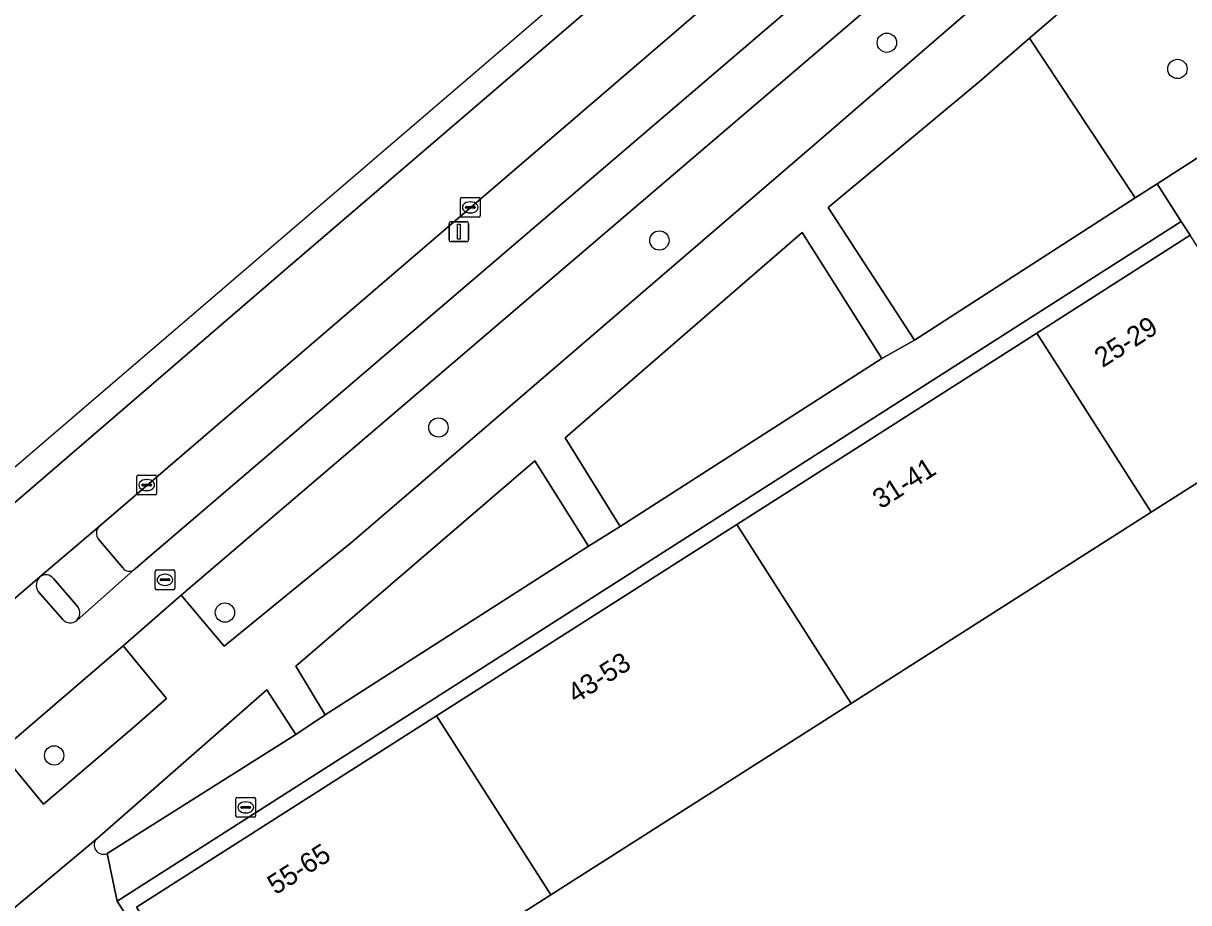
# Model space of a CAD drawing. Extents: x 159217 to 160349, y 381246 to 382172.
# Drawn here: x 159311.1 to 159370.1, y 381328.4 to 381372.9 of the extents above; entities that cross this region are included whole.
import ezdxf

# ---------------------------------------------------------------- set-up
doc = ezdxf.new("R2010")
doc.units = 0
for name, color, linetype in [('IMGEO_Berm_groen', 7, 'Continuous'), ('IMGEO_Boom', 7, 'Continuous'), ('IMGEO_Brandkraan', 7, 'Continuous'), ('IMGEO_Fietspad_gesloten', 7, 'Continuous'), ('IMGEO_Groenvoorziening', 7, 'Continuous'), ('IMGEO_Haag', 7, 'Continuous'), ('IMGEO_Kolk', 7, 'Continuous'), ('IMGEO_Lichtmast', 7, 'Continuous'), ('IMGEO_Pand', 7, 'Continuous'), ('IMGEO_Pand_nummerreeks', 7, 'Continuous'), ('IMGEO_Rijbaan_regionaal_gesloten', 7, 'Continuous'), ('IMGEO_Rioolput', 7, 'Continuous'), ('IMGEO_Verkeerseiland_gesloten', 7, 'Continuous'), ('IMGEO_Voetpad_gesloten', 7, 'Continuous'), ('IMGEO_Voetpad_open', 7, 'Continuous')]:
    doc.layers.add(name, color=color, linetype=linetype)

msp = doc.modelspace()

# ---------------------------------------------------------------- linework, layer by layer
at = {"layer": 'IMGEO_Berm_groen'}
for points in [[(159541.413, 381548.895), (159529.847, 381537.235), (159512.119, 381520.34), (159494.844, 381504.328), (159477.455, 381488.498), (159459.899, 381472.744), (159441.511, 381456.538), (159423.028, 381440.428), (159418.061, 381436.145), (159368.742, 381393.618), (159314.99, 381347.48)], [(159316.719, 381345.255), (159370.524, 381391.273), (159389.279, 381407.409), (159420.07, 381433.95), (159424.841, 381438.063), (159443.296, 381454.096)], [(159314.944, 381346.814), (159316.169, 381345.364)]]:
    msp.add_lwpolyline(points, dxfattribs=at)
for centre, radius, start, end in [((159315.325, 381347.122), 0.49, 133.1012, 218.99662), ((159316.508, 381345.631), 0.432, 218.28105, 299.29949)]:
    msp.add_arc(centre, radius, start, end, dxfattribs=at)
at = {"layer": 'IMGEO_Boom'}
for centre in [(159354.817, 381371.914), (159369.512, 381370.588), (159343.311, 381361.918), (159332.137, 381352.465), (159321.337, 381343.11), (159312.7, 381335.887)]:
    msp.add_circle(centre, 0.489, dxfattribs=at)
at = {"layer": 'IMGEO_Brandkraan'}
for p, q in [((159321.89, 381332.835), (159321.89, 381333.687)), ((159321.965, 381333.761), (159322.817, 381333.761)), ((159322.378, 381333.541), (159322.403, 381333.541)), ((159322.891, 381333.687), (159322.891, 381332.835)), ((159322.817, 381332.761), (159321.965, 381332.761)), ((159322.149, 381333.255), (159322.149, 381333.267)), ((159322.587, 381333.218), (159322.189, 381333.218)), ((159322.192, 381333.304), (159322.59, 381333.304)), ((159322.401, 381332.981), (159322.376, 381332.981)), ((159322.633, 381333.267), (159322.633, 381333.255))]:
    msp.add_line(p, q, dxfattribs=at)
for points in [[(159321.89, 381332.835), (159321.89, 381333.687)], [(159321.965, 381333.761), (159322.817, 381333.761)], [(159322.891, 381333.687), (159322.891, 381332.835)], [(159322.817, 381332.761), (159321.965, 381332.761)]]:
    msp.add_lwpolyline(points, dxfattribs=at)
for centre, radius, start, end in [((159321.967, 381333.685), 0.0765, 91.55205, 178.44795), ((159321.967, 381333.685), 0.0765, 91.55205, 178.44795), ((159322.815, 381333.685), 0.0765, 1.55205, 88.44795), ((159322.815, 381333.685), 0.0765, 1.55205, 88.44795), ((159321.967, 381332.837), 0.0765, 181.55205, 268.44795), ((159321.967, 381332.837), 0.0765, 181.55205, 268.44795), ((159322.189, 381333.264), 0.0403, 85.87752, 175.75265), ((159322.186, 381333.254), 0.0366, 178.93798, 274.71019), ((159322.59, 381333.261), 0.043, 264.86636, 352.45326), ((159322.594, 381333.266), 0.0386, 1.73085, 96.63898), ((159322.815, 381332.837), 0.0765, 271.55205, 358.44795), ((159322.815, 381332.837), 0.0765, 271.55205, 358.44795)]:
    msp.add_arc(centre, radius, start, end, dxfattribs=at)
for centre, major_axis, ratio, start_param, end_param in [((159322.377, 381333.261), (-0.387, 0.002), 0.722429, 4.712389, 7.853982), ((159322.402, 381333.261), (-0.39, 0.002), 0.717154, 1.570796, 4.712389)]:
    msp.add_ellipse(centre, major_axis=major_axis, ratio=ratio, start_param=start_param, end_param=end_param, dxfattribs=at)
at = {"layer": 'IMGEO_Fietspad_gesloten'}
for points in [[(159421.87, 381432.179), (159420.07, 381433.95), (159389.279, 381407.409), (159370.524, 381391.273), (159316.719, 381345.255), (159313.84, 381342.715)], [(159266.717, 381298.896), (159307.668, 381334.081), (159309.959, 381336.09), (159316.196, 381341.437), (159319.126, 381343.993), (159365.648, 381383.732), (159367.909, 381385.721), (159421.87, 381432.179)], [(159311.981, 381344.917), (159308.559, 381341.983)], [(159313.138, 381342.752), (159311.887, 381344.183)]]:
    msp.add_lwpolyline(points, dxfattribs=at)
for centre, radius, start, end in [((159312.382, 381344.493), 0.584, 133.40644, 211.99779), ((159313.508, 381343.087), 0.499, 222.2252, 311.74066)]:
    msp.add_arc(centre, radius, start, end, dxfattribs=at)
at = {"layer": 'IMGEO_Groenvoorziening'}
for points in [[(159351.249, 381366.858), (159363.768, 381377.666), (159367.704, 381381.089), (159367.818, 381381.186), (159365.648, 381383.732), (159319.126, 381343.993), (159321.298, 381341.413), (159326.523, 381345.675), (159327.755, 381346.666), (159339.377, 381356.652)], [(159368.979, 381378.134), (159362.036, 381372.138), (159367.369, 381364.066), (159368.485, 381364.785), (159374.871, 381368.899)], [(159367.369, 381364.066), (159362.036, 381372.138), (159359.483, 381369.933), (159351.84, 381363.588), (159356.208, 381356.877)], [(159354.568, 381355.954), (159350.524, 381362.325), (159338.537, 381351.944), (159341.33, 381347.454)], [(159339.732, 381346.46), (159337.004, 381350.772), (159324.922, 381340.396), (159326.406, 381337.947)], [(159316.743, 381337.341), (159318.385, 381338.772), (159316.196, 381341.437), (159309.959, 381336.09), (159312.169, 381333.423)]]:
    msp.add_lwpolyline(points, close=True, dxfattribs=at)
for points in [[(159371.796, 381350.484), (159368.19, 381348.187), (159353.009, 381338.515), (159337.828, 381328.844), (159322.647, 381319.172), (159316.859, 381328.222), (159332.04, 381337.894), (159347.221, 381347.565), (159362.402, 381357.237), (159370.16, 381362.179), (159369.708, 381362.882), (159315.892, 381328.525), (159322.032, 381318.947), (159324.458, 381309.034), (159328.024, 381308.61), (159328.245, 381308.652), (159328.048, 381310.17), (159378.79, 381319.78)], [(159324.921, 381336.947), (159323.453, 381339.211), (159314.871, 381331.695)], [(159315.374, 381330.929), (159324.921, 381336.947)]]:
    msp.add_lwpolyline(points, dxfattribs=at)
msp.add_arc((159315.192, 381331.358), 0.466, 133.64243, 292.94001, dxfattribs=at)
at = {"layer": 'IMGEO_Haag'}
for points in [[(159367.818, 381381.186), (159365.648, 381383.732), (159319.126, 381343.993), (159321.298, 381341.413), (159326.523, 381345.675), (159327.755, 381346.666), (159339.377, 381356.652), (159351.249, 381366.858), (159363.768, 381377.666), (159367.704, 381381.089)], [(159316.743, 381337.341), (159318.385, 381338.772), (159316.196, 381341.437), (159309.959, 381336.09), (159312.169, 381333.423)]]:
    msp.add_lwpolyline(points, close=True, dxfattribs=at)
at = {"layer": 'IMGEO_Kolk'}
for p, q in [((159333.247, 381363.164), (159333.247, 381364.016)), ((159333.322, 381364.09), (159334.174, 381364.09)), ((159334.248, 381364.016), (159334.248, 381363.164)), ((159333.506, 381363.584), (159333.506, 381363.596)), ((159333.944, 381363.547), (159333.546, 381363.547)), ((159333.549, 381363.633), (159333.947, 381363.633)), ((159333.735, 381363.87), (159333.76, 381363.87)), ((159333.99, 381363.596), (159333.99, 381363.584)), ((159334.174, 381363.09), (159333.322, 381363.09)), ((159333.758, 381363.31), (159333.733, 381363.31)), ((159316.882, 381349.131), (159316.882, 381349.983)), ((159316.957, 381350.057), (159317.809, 381350.057)), ((159317.883, 381349.983), (159317.883, 381349.131)), ((159317.141, 381349.551), (159317.141, 381349.563)), ((159317.579, 381349.514), (159317.181, 381349.514)), ((159317.184, 381349.6), (159317.582, 381349.6)), ((159317.393, 381349.277), (159317.368, 381349.277)), ((159317.37, 381349.837), (159317.395, 381349.837)), ((159317.625, 381349.563), (159317.625, 381349.551)), ((159317.809, 381349.057), (159316.957, 381349.057))]:
    msp.add_line(p, q, dxfattribs=at)
for points in [[(159333.247, 381363.164), (159333.247, 381364.016)], [(159333.322, 381364.09), (159334.174, 381364.09)], [(159334.248, 381364.016), (159334.248, 381363.164)], [(159334.174, 381363.09), (159333.322, 381363.09)], [(159316.882, 381349.131), (159316.882, 381349.983)], [(159316.957, 381350.057), (159317.809, 381350.057)], [(159317.883, 381349.983), (159317.883, 381349.131)], [(159317.809, 381349.057), (159316.957, 381349.057)]]:
    msp.add_lwpolyline(points, dxfattribs=at)
for centre, radius, start, end in [((159333.324, 381364.014), 0.0765, 91.55205, 178.44795), ((159333.324, 381364.014), 0.0765, 91.55205, 178.44795), ((159334.172, 381364.014), 0.0765, 1.55205, 88.44795), ((159334.172, 381364.014), 0.0765, 1.55205, 88.44795), ((159333.546, 381363.593), 0.0403, 85.87752, 175.75265), ((159333.543, 381363.583), 0.0366, 178.93798, 274.71019), ((159333.947, 381363.59), 0.043, 264.86636, 352.45326), ((159333.951, 381363.595), 0.0386, 1.73085, 96.63898), ((159333.324, 381363.166), 0.0765, 181.55205, 268.44795), ((159333.324, 381363.166), 0.0765, 181.55205, 268.44795), ((159334.172, 381363.166), 0.0765, 271.55205, 358.44795), ((159334.172, 381363.166), 0.0765, 271.55205, 358.44795), ((159316.959, 381349.981), 0.0765, 91.55205, 178.44795), ((159316.959, 381349.981), 0.0765, 91.55205, 178.44795), ((159317.807, 381349.981), 0.0765, 1.55205, 88.44795), ((159317.807, 381349.981), 0.0765, 1.55205, 88.44795), ((159317.181, 381349.56), 0.0403, 85.87752, 175.75265), ((159317.178, 381349.55), 0.0366, 178.93798, 274.71019), ((159317.582, 381349.557), 0.043, 264.86636, 352.45326), ((159317.586, 381349.562), 0.0386, 1.73085, 96.63898), ((159316.959, 381349.133), 0.0765, 181.55205, 268.44795), ((159316.959, 381349.133), 0.0765, 181.55205, 268.44795), ((159317.807, 381349.133), 0.0765, 271.55205, 358.44795), ((159317.807, 381349.133), 0.0765, 271.55205, 358.44795)]:
    msp.add_arc(centre, radius, start, end, dxfattribs=at)
for centre, major_axis, ratio, start_param, end_param in [((159333.734, 381363.59), (-0.387, 0.002), 0.722429, 4.712389, 7.853982), ((159333.759, 381363.59), (-0.39, 0.002), 0.717154, 1.570796, 4.712389), ((159317.369, 381349.557), (-0.387, 0.002), 0.722429, 4.712389, 7.853982), ((159317.394, 381349.557), (-0.39, 0.002), 0.717154, 1.570796, 4.712389)]:
    msp.add_ellipse(centre, major_axis=major_axis, ratio=ratio, start_param=start_param, end_param=end_param, dxfattribs=at)
at = {"layer": 'IMGEO_Lichtmast'}
for p, q in [((159332.772, 381362.862), (159333.562, 381362.862)), ((159333.562, 381362.862), (159332.772, 381362.862)), ((159332.672, 381361.962), (159332.672, 381362.762)), ((159332.672, 381362.762), (159332.672, 381361.962)), ((159333.662, 381362.762), (159333.662, 381361.962)), ((159333.662, 381361.962), (159333.662, 381362.762)), ((159333.562, 381361.862), (159332.772, 381361.862)), ((159332.772, 381361.862), (159333.562, 381361.862))]:
    msp.add_line(p, q, dxfattribs=at)
msp.add_lwpolyline([(159333.092, 381362.737), (159333.242, 381362.737), (159333.242, 381361.987), (159333.092, 381361.987), (159333.092, 381362.737)], dxfattribs=at)
for centre, start, end in [((159332.772, 381362.762), 90, 180), ((159332.772, 381362.762), 90, 180), ((159333.562, 381362.762), 0, 90), ((159333.562, 381362.762), 360, 90), ((159332.772, 381361.962), 180, 270), ((159332.772, 381361.962), 180, 270), ((159333.562, 381361.962), 270, 0), ((159333.562, 381361.962), 270, 0)]:
    msp.add_arc(centre, 0.1, start, end, dxfattribs=at)
at = {"layer": 'IMGEO_Pand'}
for points in [[(159368.19, 381348.187), (159371.796, 381350.484), (159375.948, 381353.129), (159375.362, 381354.045), (159370.16, 381362.179), (159362.402, 381357.237)], [(159347.221, 381347.565), (159353.009, 381338.515), (159368.19, 381348.187), (159362.402, 381357.237)], [(159347.221, 381347.565), (159332.04, 381337.894), (159337.828, 381328.844), (159353.009, 381338.515)], [(159332.04, 381337.894), (159316.859, 381328.222), (159322.647, 381319.172), (159337.828, 381328.844)]]:
    msp.add_lwpolyline(points, close=True, dxfattribs=at)
at = {"layer": 'IMGEO_Rijbaan_regionaal_gesloten'}
msp.add_lwpolyline([(159228.975, 381280.421), (159229.556, 381279.016), (159230.993, 381280.283), (159257.871, 381303.377), (159275.726, 381318.676), (159298.757, 381338.404), (159324.046, 381360.145), (159356.713, 381388.171), (159392.4, 381418.769), (159416.187, 381439.228), (159422.086, 381444.356), (159436.866, 381457.249), (159457.404, 381475.301), (159486.523, 381501.565), (159504.485, 381518.126), (159518.714, 381531.585), (159532.766, 381545.256), (159538.334, 381550.862), (159538.89, 381551.435), (159537.905, 381552.349), (159489.887, 381508.356), (159416.77, 381441.367), (159306.518, 381346.877)], close=True, dxfattribs=at)
msp.add_lwpolyline([(159392.4, 381418.769), (159356.713, 381388.171), (159324.046, 381360.145), (159298.757, 381338.404), (159275.726, 381318.676), (159257.871, 381303.377), (159230.993, 381280.283), (159229.556, 381279.016), (159231.026, 381275.463), (159231.671, 381276.03), (159233.805, 381277.906), (159308.559, 381341.983), (159311.981, 381344.917), (159314.99, 381347.48), (159368.742, 381393.618), (159418.061, 381436.145)], dxfattribs=at)
at = {"layer": 'IMGEO_Rioolput'}
for p, q in [((159317.805, 381344.34), (159317.805, 381345.192)), ((159317.88, 381345.266), (159318.732, 381345.266)), ((159318.806, 381345.192), (159318.806, 381344.34)), ((159318.064, 381344.76), (159318.064, 381344.772)), ((159318.502, 381344.723), (159318.104, 381344.723)), ((159318.107, 381344.809), (159318.505, 381344.809)), ((159318.293, 381345.046), (159318.318, 381345.046)), ((159318.548, 381344.772), (159318.548, 381344.76)), ((159318.732, 381344.266), (159317.88, 381344.266)), ((159318.316, 381344.486), (159318.291, 381344.486))]:
    msp.add_line(p, q, dxfattribs=at)
for points in [[(159317.805, 381344.34), (159317.805, 381345.192)], [(159317.88, 381345.266), (159318.732, 381345.266)], [(159318.806, 381345.192), (159318.806, 381344.34)], [(159318.732, 381344.266), (159317.88, 381344.266)]]:
    msp.add_lwpolyline(points, dxfattribs=at)
for centre, radius, start, end in [((159317.882, 381345.19), 0.0765, 91.55205, 178.44795), ((159317.882, 381345.19), 0.0765, 91.55205, 178.44795), ((159318.73, 381345.19), 0.0765, 1.55205, 88.44795), ((159318.73, 381345.19), 0.0765, 1.55205, 88.44795), ((159318.104, 381344.769), 0.0403, 85.87752, 175.75265), ((159318.101, 381344.759), 0.0366, 178.93798, 274.71019), ((159318.505, 381344.766), 0.043, 264.86636, 352.45326), ((159318.509, 381344.771), 0.0386, 1.73085, 96.63898), ((159317.882, 381344.342), 0.0765, 181.55205, 268.44795), ((159317.882, 381344.342), 0.0765, 181.55205, 268.44795), ((159318.73, 381344.342), 0.0765, 271.55205, 358.44795), ((159318.73, 381344.342), 0.0765, 271.55205, 358.44795)]:
    msp.add_arc(centre, radius, start, end, dxfattribs=at)
for centre, major_axis, ratio, start_param, end_param in [((159318.292, 381344.766), (-0.387, 0.002), 0.722429, 4.712389, 7.853982), ((159318.317, 381344.766), (-0.39, 0.002), 0.717154, 1.570796, 4.712389)]:
    msp.add_ellipse(centre, major_axis=major_axis, ratio=ratio, start_param=start_param, end_param=end_param, dxfattribs=at)
at = {"layer": 'IMGEO_Verkeerseiland_gesloten'}
for points in [[(159313.899, 381343.399), (159312.669, 381344.838)], [(159311.887, 381344.183), (159313.138, 381342.752)]]:
    msp.add_lwpolyline(points, dxfattribs=at)
for centre, radius, start, end in [((159312.382, 381344.493), 0.584, 133.40644, 211.99779), ((159312.282, 381344.505), 0.511, 40.75431, 126.14502), ((159313.506, 381343.088), 0.501, 311.83543, 38.30462), ((159313.508, 381343.087), 0.499, 222.2252, 311.74066)]:
    msp.add_arc(centre, radius, start, end, dxfattribs=at)
at = {"layer": 'IMGEO_Voetpad_gesloten'}
for points in [[(159314.99, 381347.48), (159311.981, 381344.917)], [(159316.169, 381345.364), (159314.944, 381346.814)], [(159313.84, 381342.715), (159316.719, 381345.255)], [(159312.669, 381344.838), (159313.899, 381343.399)]]:
    msp.add_lwpolyline(points, dxfattribs=at)
for centre, radius, start, end in [((159315.325, 381347.122), 0.49, 133.1012, 218.99662), ((159316.508, 381345.631), 0.432, 218.28105, 299.29949), ((159312.282, 381344.505), 0.511, 40.75431, 126.14502), ((159313.506, 381343.088), 0.501, 311.83543, 38.30462)]:
    msp.add_arc(centre, radius, start, end, dxfattribs=at)
at = {"layer": 'IMGEO_Voetpad_open'}
for points in [[(159372.056, 381380.86), (159368.979, 381378.134), (159374.871, 381368.899), (159368.485, 381364.785), (159369.708, 381362.882), (159370.16, 381362.179)], [(159263.966, 381288.021), (159266.467, 381290.167), (159281.033, 381302.677), (159310.53, 381328.046), (159314.871, 381331.695), (159323.453, 381339.211), (159324.921, 381336.947), (159326.406, 381337.947), (159324.922, 381340.396), (159337.004, 381350.772), (159339.732, 381346.46), (159341.33, 381347.454), (159338.537, 381351.944), (159350.524, 381362.325), (159354.568, 381355.954), (159356.208, 381356.877), (159351.84, 381363.588), (159359.483, 381369.933), (159362.036, 381372.138), (159368.979, 381378.134)], [(159363.768, 381377.666), (159351.249, 381366.858), (159339.377, 381356.652), (159327.755, 381346.666), (159326.523, 381345.675), (159321.298, 381341.413), (159319.126, 381343.993), (159316.196, 381341.437), (159318.385, 381338.772), (159316.743, 381337.341), (159312.169, 381333.423), (159309.959, 381336.09), (159307.668, 381334.081), (159309.029, 381332.498), (159309.864, 381331.383), (159299.404, 381322.252), (159285.384, 381310.233), (159273.472, 381300.005), (159268.298, 381295.595), (159259.177, 381287.7), (159257.124, 381286.174), (159250.215, 381280.316), (159249.421, 381281.186)], [(159314.871, 381331.695), (159310.53, 381328.046)], [(159322.032, 381318.947), (159315.892, 381328.525), (159315.374, 381330.929)]]:
    msp.add_lwpolyline(points, dxfattribs=at)
msp.add_lwpolyline([(159369.708, 381362.882), (159368.485, 381364.785), (159367.369, 381364.066), (159356.208, 381356.877), (159354.568, 381355.954), (159341.33, 381347.454), (159339.732, 381346.46), (159326.406, 381337.947), (159324.921, 381336.947), (159315.374, 381330.929), (159315.892, 381328.525)], close=True, dxfattribs=at)
msp.add_arc((159315.192, 381331.358), 0.466, 133.64243, 292.94001, dxfattribs=at)

# ---------------------------------------------------------------- texts
at = {"layer": 'IMGEO_Pand_nummerreeks'}
for s, p in [('25-29', (159365.725, 381355.464)), ('31-41', (159354.505, 381348.316)), ('43-53', (159339.077, 381338.488)), ('55-65', (159323.896, 381328.816))]:
    msp.add_text(s, height=1, rotation=32.5004, dxfattribs=at).set_placement(p)

doc.saveas('drawing.dxf')
